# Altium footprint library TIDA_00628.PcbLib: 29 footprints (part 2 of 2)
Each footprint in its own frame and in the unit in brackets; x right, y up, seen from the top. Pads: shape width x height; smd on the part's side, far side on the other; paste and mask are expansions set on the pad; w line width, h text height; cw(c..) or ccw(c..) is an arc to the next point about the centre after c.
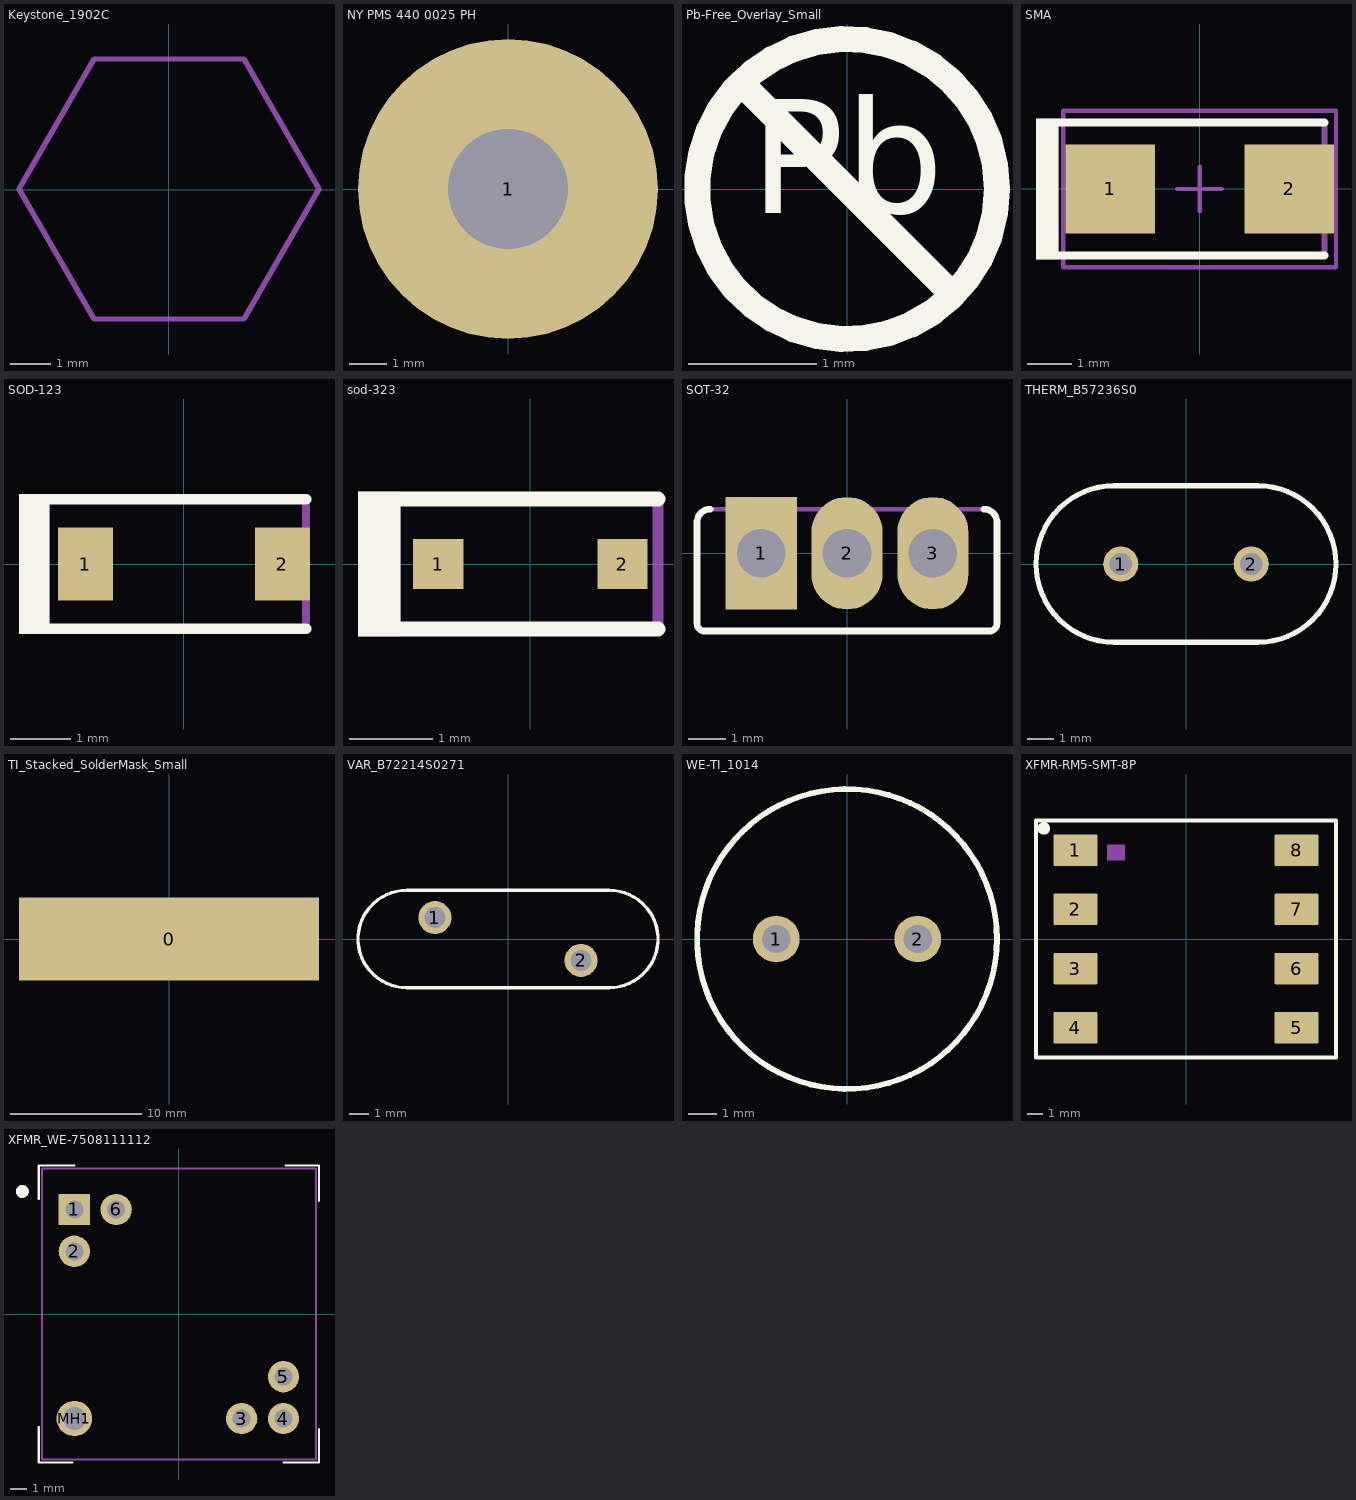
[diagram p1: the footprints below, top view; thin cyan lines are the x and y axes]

## Keystone_1902C [mm] "Hex Standoff, 4-40 threaded, nylon"
height 12.7
Mechanical 5:
  lines w0.127: -3.69,0.012 -1.843,-3.188 1.852,-3.188 3.7,0.012 1.852,3.212 -1.843,3.212 -3.69,0.012
  text ".Designator" at -1.524,-0.508 h1.02
3D body: height 12.73, standoff 0.03, extent -3.682,-3.2 3.708,3.2

## NY PMS 440 0025 PH [mm] "4-40 nylon screw and mounting hole"
height 1.905
pads (1):
  round 8 hole 3.2: 1(0,0)
Mechanical 5:
  circle w0.127: c0,0 r3.789
  text ".Designator" at -1.524,-0.508 h1.02
3D body: height 2.69, standoff -8.74, extent -3.302,-3.3 3.296,3.3

## Pb-Free_Overlay_Small [mm]
Top Overlay:
  circle w0.203: c0,0 r1.168
  lines w0.203: -0.826,0.826 0.826,-0.826
  text "Pb" at -0.752,-0.48 h1.52

## SMA [mm] "Molded Diode, 2-Leads, Body 4.3x2.6mm, IPC Medium Density, based on OnSemi component dimensions and land pattern"
height 2.27
pads (2):
  rect 2x2 smd: 1(-2,0) 2(2,0)
Top Overlay:
  rectangle: -3.658,-1.575 -3.15,1.575
  lines w0.178: -3.327,-1.486 2.794,-1.486 ; -3.327,1.486 2.794,1.486
Mechanical 5:
  rectangle: -3.658,-1.575 -3.15,1.575
  lines w0.127: -3.327,-1.486 2.794,-1.486 2.794,1.486 -3.327,1.486
  text ".Designator" at -2.769,-0.33 h1.02
Mechanical 15:
  lines w0.1: -0.5,0 0.5,0 ; 0,-0.5 0,0.5 ; -3.05,-1.75 -3.05,1.75 3.05,1.75 3.05,-1.75 -3.05,-1.75
3D body: height 2.42, standoff 0.02, extent -2.6,-1.3 2.6,1.3

## SOD-123 [mm] "On Semi recommended land pattern"
height 1.35
pads (2):
  rect 0.915x1.22 smd: 1(-1.637,0) 2(1.637,0)
Top Overlay:
  rectangle: -2.743,-1.168 -2.235,1.168
  lines w0.178: -2.413,-1.079 2.032,-1.079 ; -2.413,1.079 2.032,1.079
Mechanical 5:
  rectangle: -2.743,-1.168 -2.235,1.168
  lines w0.127: -2.413,-1.079 2.032,-1.079 2.032,1.079 -2.413,1.079
  text ".Designator" at -1.956,-0.33 h0.76
3D body: height 1.35, standoff 0, extent -1.932,-0.9 1.932,0.9

## sod-323 [mm] "NXP recommended land pattern"
height 1.15
pads (2):
  rect 0.6x0.6 smd paste-0.05: 1(-1.1,0) 2(1.1,0)
Top Overlay:
  rectangle: -2.057,-0.864 -1.549,0.864
  lines w0.178: -1.803,-0.775 0.1,-0.775 1.525,-0.775 ; -1.803,0.775 0.1,0.775 1.525,0.775
Mechanical 5:
  rectangle: -2.057,-0.864 -1.549,0.864
  lines w0.127: -1.803,-0.775 0.1,-0.775 1.525,-0.775 1.525,0.775 0.1,0.775 -1.803,0.775
  text ".Designator" at -1.4,-0.275 h0.76
3D body: height 1.1, standoff 0, extent -1.3,-0.675 1.3,0.675

## SOT-32 [mm]
height 13
pads (3):
  rect 1.9x3 hole 1.3: 1(-2.29,0)
  oval 1.9x3 hole 1.3: 2(0,0) 3(2.29,0)
Top Overlay:
  lines w0.178: -3.65,1.175 ccw(c-3.65,0.825) -3.996,0.878 ccw(c-3.65,0.825) -4,0.825 -4,-1.845 -4,-1.875 ccw(c-3.8,-1.875) -3.8,-2.075 3.8,-2.075 ccw(c3.8,-1.875) 4,-1.875 4,-1.845 4,0.825 ccw(c3.65,0.825) 3.996,0.878 ccw(c3.65,0.825) 3.65,1.175
Mechanical 5:
  lines w0.127: -4,-1.875 ccw(c-3.8,-1.875) -3.8,-2.075 3.8,-2.075 ccw(c3.8,-1.875) 4,-1.875 4,-1.845 4,0.825 ccw(c3.65,0.825) 3.996,0.878 ccw(c3.65,0.825) 3.65,1.175 -3.65,1.175 ccw(c-3.65,0.825) -3.996,0.878 ccw(c-3.65,0.825) -4,0.825 -4,-1.845 -4,-1.875
  text ".Designator" at -1.875,-0.5 h1.02
3D body: height 13.13, standoff -4.98, extent -4,-2.073 4,1.177

## THERM_B57236S0 [mm] "EPCOS"
height 16
pads (2):
  round 1.35 hole 0.85: 1(-2.5,0) 2(2.5,0)
Top Overlay:
  lines w0.2: -2.75,-3 cw(c-2.75,0) -2.75,3 2.75,3 cw(c2.75,0) 2.75,-3 -2.75,-3
Mechanical 5:
  lines w0.1: -2.75,-3 cw(c-2.75,0) -2.75,3 2.75,3 cw(c2.75,0) 2.75,-3 -2.75,-3
  text ".Designator" at -4.024,-0.508 h1.02
3D body: height 15.99, standoff 4.51, extent -5.755,-3 5.7,3
3D body: height 5.5, standoff -2.5, extent 2.202,-0.299 2.8,0.3
3D body: height 5.5, standoff -2.5, extent -2.797,-0.299 -2.2,0.3

## TI_Stacked_SolderMask_Small [mm]
pads (1):
  rect 22.86x6.35 smd paste-3.175 mask-3.175: 0(0,0)
Top Solder:
  drawing of 18 lines, arcs and shapes, not listed

## VAR_B72214S0271 [mm] "EPCOS"
height 18.5
pads (2):
  round 1.7 hole 1.067: 1(-3.75,1.1) 2(3.75,-1.1)
Top Overlay:
  lines w0.17: -5.2,-2.5 cw(c-5.2,0) -5.2,2.5 5.2,2.5 cw(c5.2,0) 5.2,-2.5 -5.2,-2.5
Mechanical 5:
  lines w0.1: -5.3,-2.5 5.2,-2.5 ccw(c5.2,0) 5.2,2.5 -5.3,2.5 ; -5.2,-2.5 cw(c-5.2,0) -5.2,2.5
  text ".Designator" at -1.8,-0.5 h1.02
3D body: height 18.48, standoff 3.02, extent -7.739,-2.5 7.7,2.5
3D body: height 6, standoff -2, extent -4.172,0.676 -3.325,1.524
3D body: height 6, standoff -2, extent 3.328,-1.524 4.175,-0.676

## WE-TI_1014 [mm] "WURTH"
height 14.5
pads (2):
  round 1.65 hole 1: 1(-2.5,0) 2(2.5,0)
Top Overlay:
  circle w0.2: c0,0 r5.3
Mechanical 5:
  circle w0.1: c0,0 r5.25
  text ".Designator" at -1.8,-0.5 h1.02
3D body: height 1, standoff -2, extent -2.847,-0.349 -2.15,0.35
3D body: height 1, standoff -2, extent 2.153,-0.349 2.85,0.35
3D body: height 14.5, standoff 13.5, extent -5.261,-5.261 5.261,5.261
3D body: height 13.5, standoff 4, extent -4.91,-4.91 4.91,4.91
3D body: height 4, standoff 0, extent -5.261,-5.261 5.261,5.261

## XFMR-RM5-SMT-8P [mm]
pads (8):
  rrect10% 2.8x2 smd: 1(-7,5.625) 2(-7,1.875) 3(-7,-1.875) 4(-7,-5.625) 5(7,-5.625) 6(7,-1.875) 7(7,1.875) 8(7,5.625)
Top Overlay:
  circle w0.381: c-9,7 r0.203
  lines w0.25: -9.5,-7.5 -9.5,7.5 9.5,7.5 9.5,-7.5 -9.5,-7.5
Mechanical 5:
  rectangle: -5,4.984 -3.857,6
  lines w0.127: -9.5,-7.5 9.5,-7.5 9.5,7.5 -9.5,7.5 -9.5,-7.5
  text ".Designator" at -3.175,-0.127 h1.02

## XFMR_WE-7508111112 [mil]
height 520
pads (7):
  rect 75x75 hole 43: 1(-250,250)
  round 75 hole 43: 2(-250,150) 3(150,-250) 4(250,-250) 5(250,-150) 6(-150,250)
  round 85 hole 55: MH1(-250,-250)
Top Overlay:
  circle w15: c-374.32,293 r8
  lines w5: -335,-270 -335,-355 -255,-355 ; -335,275 -335,355 -250,355 ; 250,-355 335,-355 335,-275 ; 255,355 335,355 335,270
Mechanical 5:
  circle w5: c149,-250 r10
  circle w5: c249,-150 r10
  circle w5: c-251,150 r10
  circle w5: c-151,250 r10
  rectangle: -275,230 -230,270
  lines w5: -327.5,-347.5 -327.5,347.5 327.5,347.5 327.5,-347.5 -327.5,-347.5
  text ".Designator" at -125,-5 h40
3D body: height 0, standoff -120, extent -262.75,243.57 -249.9,256.43
3D body: height 0, standoff -120, extent 138.82,-260.18 159.18,-239.82
3D body: height 0, standoff -120, extent 238.82,-160.18 259.18,-139.82
3D body: height 0, standoff -120, extent -161.18,239.82 -140.82,260.18
3D body: height 0, standoff -120, extent -261.18,139.82 -240.82,160.18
